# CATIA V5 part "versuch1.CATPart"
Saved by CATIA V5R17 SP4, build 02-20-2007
Part number: Guss-Konstruktion SP
Bounding box of the stored display mesh (mm): x 0 to 266.803, y -87 to 87, z -230 to 255
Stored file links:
  D:\Dokumente und Einstellungen\Alexander\Eigene Dateien\versuch1.CATPart
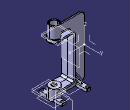
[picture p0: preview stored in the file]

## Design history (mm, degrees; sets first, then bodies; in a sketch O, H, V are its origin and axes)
AxisSystem1: origin (0, 0, 0), X (1, 0, 0), Y (0, 1, 0), Z (0, 0, 1)
Sketch1 on Plane2, origin (0, 0, 170), H (1, 0, 0), V (0, 1, 0)
  line L1 (125, 45) -> (267, 45)
  line L2 (267, 45) -> (267, -45)
  line L3 (267, -45) -> (125, -45)
  line L4 (125, -45) -> (125, 45)
  reference projected line E1 (110, -45) -> (125, -45) from edge [face of Pad2 from Sketch2.L4 | face of Pad2 from Sketch2.L1]
  reference projected line E2 (110, 45) -> (125, 45) from edge [face of Pad2 from Sketch2.L1 | face of Pad2 from Sketch2.L2]
  reference projected line E3 (125, 60) -> (125, -60) from edge [face of Pad2 from Sketch2.L1 | end face of Pad2]
  length L3 = 142
  horizontal: L1 H, L3 H
  vertical: L2 V, L4 V
  coincidence: L3 E1, L1 E2, L4 E3
Pad1: profile Sketch1, direction (0, 0, -1), length 15
Sketch2 on face of Pad3 from Sketch3.L14, origin (110, 0, 0), H (0, 1, 0), V (0, 0, 1)
  line L1 (-45, 170) -> (45, 170)
  line L2 (45, 170) -> (45, -170)
  line L3 (45, -170) -> (-45, -170)
  line L4 (-45, -170) -> (-45, 170)
  reference intersected line E1 through (0, 170) direction (-1, 0) from Plane2
  length L3 = 90
  horizontal: L1 H, L3 H
  vertical: L2 V, L4 V
  symmetry: L3 L1 H, L2 L4 V
  coincidence: L1 E1
Pad2: profile Sketch2, direction (1, 0, 0), length 15
Set1
  Plane1: type Offset, RefPlane face of Pad3 from Sketch3.L13, Offset 0
  Plane2: type Offset, RefPlane face of Pad3 from Sketch3.L15, Offset 0, reversed
  Plane3: type Offset, RefPlane face of Pad3 from Sketch3.L14, Offset 0
  Plane4: type Offset, RefPlane Plane2, Offset 10, reversed
  Plane5: type Offset, RefPlane Plane1, Offset 15, reversed
  Plane6: type Offset, RefPlane face of Pad3 from Sketch3.L11, Offset 0, reversed
  Plane7: type Offset, RefPlane face of Pad8 from Sketch12.L8, Offset 17.5
  Plane8: type Offset, RefPlane face of Pad8, Offset 0, reversed
Body1 (main body)
  Sketch3 on zx-plane, origin (0, 0, 0), H (-1, 0, 0), V (0, 0, 1)
    construction line L1 (-192, 230) -> (0, 230)
    point P1 (0, 230)
    construction line L2 (0, 230) -> (0, -230)
    construction line L3 (0, -230) -> (-265, -230)
    construction line L4 (-265, -230) -> (-265, -170)
    construction line L5 (-265, -170) -> (-110, -170)
    construction line L6 (-110, -170) -> (-110, 170)
    construction line L7 (-110, 170) -> (-192, 170)
    construction line L8 (-192, 170) -> (-192, 230)
    line L9 (-192, 230) -> (0, 230)
    line L10 (0, 230) -> (0, -230)
    line L11 (0, -230) -> (-265, -230)
    line L12 (-265, -230) -> (-265, -170)
    line L13 (-265, -170) -> (-110, -170)
    line L14 (-110, -170) -> (-110, 170)
    line L15 (-110, 170) -> (-192, 170)
    line L16 (-192, 170) -> (-192, 230)
    reference projected line E1 through (0, 0) direction (-1, 0) from edge [XY plane of AxisSystem1 | ZX plane of AxisSystem1]
    reference intersected line E2 through (0, 0) direction (-1, 0) from XY plane of AxisSystem1
    distance L14 L10 = 110
    distance L13 L11 = 60
    distance L16 L10 = 192
    length L10 = 460
    length L11 = 265
    coincidence: P1 V
    horizontal: L1 H, L3 H, L5 H, L7 H, L9 H, L11 H, L13 H, L15 H
    vertical: L2 V, L4 V, L6 V, L8 V, L10 V, L12 V, L14 V, L16 V
    symmetry: L15 L13 E1, L9 L11 E2
  Pad3: profile Sketch3, direction (0, 1, 0), length 6, mirrored extent
  Fillet1: radius 40, on edge [face of Pad3 from Sketch3.L10 | face of Pad3 from Sketch3.L11]
  Fillet2: radius 40, on edge [face of Pad3 from Sketch3.L9 | face of Pad3 from Sketch3.L10]
  Fillet3: radius 12, on edge [end face of Pad1 | end face of Pad2]
  Fillet4: radius 27, on edge [start face of Pad2 | face of Pad1] (x2)
  Sketch4 on Plane4, origin (0, 0, 160), H (1, 0, 0), V (0, 1, 0)
    circle A1 centre (224.8029, 0) radius 42
    point P1 (224.8029, 0)
    point P2 (182.8029, 0)
    circle A2 centre (224.8029, 0) radius 26
    radius A1 = 42
    radius A2 = 26
    coincidence: P1 H, A1 P2, P2 H
  Pad4: profile Sketch4, direction (0, 0, -1), length 15
  Sketch5 on Plane4, origin (0, 0, 160), H (1, 0, 0), V (0, 1, 0)
    line L1 (217.723, 45) -> (234.8496, 40.7807)
    point P1 (217.723, 45)
    point P2 (234.8496, 40.7807)
    reference projected line E1 (267, 45) -> (125, 45) from edge [end face of Pad1 | face of Pad1]
    reference projected circle E2 centre (224.8029, 0) radius 42 from edge [face of Pad4 from Sketch4.A1 | end face of Pad1]
    reference projected circle E3 centre (224.8029, 0) radius 42 from edge [face of Pad4 from Sketch4.A1 | end face of Pad1]
    line L2 (217.723, -45) -> (234.8496, -40.7807)
    point P3 (217.723, -45)
    point P4 (234.8496, -40.7807)
    reference projected line E4 (125, -45) -> (267, -45) from edge [end face of Pad1 | face of Pad1]
    reference projected circle E5 centre (224.8029, 0) radius 42 from edge [face of Pad4 from Sketch4.A1 | end face of Pad1]
    reference projected circle E6 centre (224.8029, 0) radius 42 from edge [face of Pad4 from Sketch4.A1 | end face of Pad1]
    arc A1 centre (224.8029, 0) radius 42 from (234.8496, -40.7807) to (234.8496, 40.7807) ccw
    point P5 (224.8029, 0)
    reference projected circle E7 centre (224.8029, 0) radius 26 from edge [end face of Pad1 | face of Pad4 from Sketch4.A2]
    line L3 (217.723, -45) -> (267.8976, -45)
    line L4 (267.8976, -45) -> (267.8976, 45)
    line L5 (267.8976, 45) -> (217.723, 45)
    coincidence: P1 E1, P2 E2, P3 E4, P4 E5, P5 H
    tangency: L1 E3, L2 E6
    concentricity: A1 E7
    horizontal: L3 H, L5 H
    vertical: L4 V
  Pocket1: profile Sketch5, direction (0, 0, 1), length 10, mirrored extent
  Sketch6 on end face of Pad1, origin (217.5608, 1.8006, 155), H (1, 0, 0), V (0, -1, 0)
    point P1 (7.2421, 1.8006)
    reference projected circle E1 centre (7.2421, 1.8006) radius 26 from edge [end face of Pad1 | face of Pad4 from Sketch4.A2]
    concentricity: P1 E1
  Hole1: placed by Sketch6, at (224.8029, 0, 155) direction (0, 0, 1), diameter 52, through (limit type 6)
  Sketch7 on Plane2, origin (0, 0, 170), H (1, 0, 0), V (0, 1, 0)
    circle A1 centre (224.8029, 0) radius 36
    point P1 (224.8029, 0)
    reference projected circle E1 centre (224.8029, 0) radius 26 from edge [face of Pad1 | face of Hole1]
    circle A2 centre (224.8029, 0) radius 26
    radius A1 = 36
    radius A2 = 26
    coincidence: P1 H
    concentricity: A1 E1
  Pad5: profile Sketch7, direction (0, 0, 1), length 85
  Sketch8 on Plane1, origin (0, 0, -170), H (1, 0, 0), V (0, -1, 0)
    line L1 (265, 45) -> (125, 45)
    line L2 (125, 45) -> (125, -45)
    line L3 (125, -45) -> (265, -45)
    line L4 (265, -45) -> (265, 45)
    reference intersected line E1 through (0, 0) direction (1, 0) from ZX plane of AxisSystem1
    reference projected line E2 (125, 60) -> (125, -60) from edge [face of Pad2 from Sketch2.L3 | end face of Pad2]
    reference projected line E3 (265, 12) -> (265, -12) from edge [face of Pad3 from Sketch3.L12 | face of Pad3 from Sketch3.L13]
    length L4 = 90
    horizontal: L1 H, L3 H
    vertical: L2 V, L4 V
    symmetry: L1 L3 E1
    coincidence: L2 E2, L4 E3
  Pad6: profile Sketch8, direction (0, 0, 1), length 15
  Sketch9 on Plane1, origin (0, 0, -170), H (1, 0, 0), V (0, -1, 0)
    circle A1 centre (224.8029, 0) radius 40
    point P1 (224.8029, 0)
    point P2 (184.8029, 0)
    circle A2 centre (224.8029, 0) radius 15
    point P3 (209.8029, 0)
    reference projected circle E1 centre (224.8029, 0) radius 26 from edge [end face of Pad5 | face of Pad5 from Sketch7.A2]
    radius A1 = 40
    radius A2 = 15
    coincidence: P1 H, A1 P2, P2 H, A2 P3, P3 H
    concentricity: A1 E1
  Pad7: profile Sketch9, direction (0, 0, 1), length 25
  Sketch10 on Plane5, origin (0, 0, -155), H (1, 0, 0), V (0, -1, 0)
    line L1 (210.4501, -45) -> (234.7765, -38.7366)
    point P1 (210.4501, -45)
    point P2 (234.7765, -38.7366)
    reference projected line E1 (125, -45) -> (265, -45) from edge [end face of Pad6 | face of Pad6]
    reference projected circle E2 centre (224.8029, 0) radius 40 from edge [face of Pad7 from Sketch9.A1 | end face of Pad6]
    reference projected circle E3 centre (224.8029, 0) radius 40 from edge [face of Pad7 from Sketch9.A1 | end face of Pad6]
    line L2 (208.5936, 45) -> (234.1002, 38.9045)
    point P3 (208.5936, 45)
    point P4 (234.1002, 38.9045)
    reference projected line E4 (265, 45) -> (125, 45) from edge [end face of Pad6 | face of Pad6]
    reference projected circle E5 centre (224.8029, 0) radius 40 from edge [face of Pad7 from Sketch9.A1 | end face of Pad6]
    reference projected circle E6 centre (224.8029, 0) radius 40 from edge [face of Pad7 from Sketch9.A1 | end face of Pad6]
    arc A1 centre (224.8029, 0) radius 40 from (234.7765, -38.7366) to (234.1002, 38.9045) ccw
    point P5 (224.8029, 0)
    point P6 (234.7765, -38.7366)
    reference projected circle E7 centre (224.8029, 0) radius 15 from edge [end face of Pad6 | face of Pad7 from Sketch9.A2]
    line L3 (210.4501, -45) -> (266.7285, -45)
    line L4 (266.7285, -45) -> (266.7285, 45)
    line L5 (266.7285, 45) -> (208.5936, 45)
    coincidence: P1 E1, P2 E2, P3 E4, P4 E5, P5 H, P6 L1, P2 P6
    tangency: L1 E3, L2 E6
    concentricity: A1 E7
    horizontal: L3 H, L5 H
    vertical: L4 V
  Pocket2: profile Sketch10, direction (0, 0, -1), through (limit type 6)
  Fillet5: radius 12, on edge [end face of Pad6 | end face of Pad2]
  Fillet6: radius 27, on edge [start face of Pad2 | face of Pad7] (x2)
  Sketch11 on end face of Pad6, origin (218.285, 2.7316, -155), H (1, 0, 0), V (0, 1, 0)
    point P1 (6.5179, -2.7316)
    reference projected circle E1 centre (6.5179, -2.7316) radius 15 from edge [end face of Pad6 | face of Pad7 from Sketch9.A2]
    concentricity: P1 E1
  Hole2: placed by Sketch11, at (224.8029, 0, -155) direction (0, 0, -1), diameter 30, depth 20
  Draft1: PullDir ZX plane of AxisSystem1, Parting ZX plane of AxisSystem1, Angle 2, SupportToDraft start face of Pad2, Neutral ZX plane of AxisSystem1
  Draft2: PullDir ZX plane of AxisSystem1, Parting ZX plane of AxisSystem1, Angle 2, SupportToDraft start face of Pad2, Neutral ZX plane of AxisSystem1
  Draft3: PullDir ZX plane of AxisSystem1, Parting ZX plane of AxisSystem1, Angle 2, SupportToDraft end face of Pad2, Neutral ZX plane of AxisSystem1
  Draft4: PullDir ZX plane of AxisSystem1, Parting ZX plane of AxisSystem1, Angle 2, SupportToDraft end face of Pad2, Neutral ZX plane of AxisSystem1
  Sketch12 on Plane6, origin (0, 0, -230), H (1, 0, 0), V (0, 1, 0)
    line L1 (70, 87) -> (35, 87)
    line L2 (35, 87) -> (35, -87)
    line L3 (35, -87) -> (70, -87)
    line L4 (70, -87) -> (70, 87)
    reference intersected line E1 through (0, 0) direction (-1, 0) from ZX plane of AxisSystem1
    reference intersected line E2 through (110, 0) direction (0, -1) from Plane3
    point P5 (254.8029, 87)
    line L5 (254.8029, 87) -> (219.8029, 87)
    line L6 (219.8029, 87) -> (219.8029, -87)
    line L7 (219.8029, -87) -> (254.8029, -87)
    line L8 (254.8029, -87) -> (254.8029, 87)
    point P7 (219.8029, -87)
    reference projected arc E3 centre (224.8029, 0) radius 40 from (262.9605, -12) to (262.9605, 12) ccw from edge [face of Pad3 from Sketch3.L11 | face of Pocket2 from Sketch10.A1]
    distance L4 E2 = 40
    length L2 = 174
    length L3 = 35
    length L7 = 35
    distance L8 E3 = 10
    horizontal: L1 H, L3 H, L5 H, L7 H
    vertical: L2 V, L4 V, L6 V, L8 V
    symmetry: L3 L1 E1
    coincidence: P5 L1, P7 L3
  Pad8: profile Sketch12, direction (0, 0, 1), length 20
  Sketch13 on ZX plane of AxisSystem1, origin (0, 0, 0), H (0, 0, 1), V (1, 0, 0)
    line L1 (-210, 46.5) -> (-185.6547, 46.5)
    line L2 (-185.6547, 46.5) -> (-122.8649, 85.2538)
    line L3 (-122.8649, 85.2538) -> (-122.8649, 111.5714)
    line L4 (-122.8649, 111.5714) -> (-134.8649, 111.5714)
    line L5 (-134.8649, 111.5714) -> (-134.8649, 91.949)
    line L6 (-134.8649, 91.949) -> (-189.0597, 58.5)
    line L7 (-189.0597, 58.5) -> (-210, 58.5)
    line L8 (-210, 58.5) -> (-210, 46.5)
    reference projected line E1 (-210, 100) -> (-210, 65) from edge [face of Pad8 from Sketch12.L1 | end face of Pad8]
    reference projected line E2 (-143, 111.5714) -> (143, 111.5714) from edge [start face of Pad2 | face of Pad6]
    reference projected line E3 (-230, 70) -> (-210, 70) from edge [face of Pad8 from Sketch12.L1 | face of Pad8 from Sketch12.L4]
    length L8 = 12
    length L4 = 12
    distance L7 E3 = 11.5
    distance L2 L6 = 12
    horizontal: L1 H, L4 H, L7 H
    vertical: L3 V, L5 V, L8 V
    coincidence: L8 E1, L4 E2
  Pad9: profile Sketch13, direction (0, 1, 0), length 35, mirrored extent
  Fillet7: radius 21, on edge [face of Pad9 from Sketch13.L3 | face of Pad9 from Sketch13.L2] (x2)
  Fillet8: radius 9, on edge [face of Pad9 from Sketch13.L6 | face of Pad9 from Sketch13.L5] (x2)
  Fillet9: radius 4, on edge [face of Pad9 from Sketch13.L2 | face of Pad9 from Sketch13.L1] (x2)
  Fillet10: radius 4, on edge [face of Pad9 from Sketch13.L7 | face of Pad9 from Sketch13.L6] (x2)
  Sketch14 on Plane5, origin (0, 0, -155), H (1, 0, 0), V (0, -1, 0)
    circle A1 centre (224.8029, 0) radius 40
    point P1 (224.8029, 0)
    reference projected circle E1 centre (224.8029, 0) radius 15 from edge [face of Hole2 | face of Pad7 from Sketch9.A2]
    circle A2 centre (224.8029, 0) radius 30
    point P2 (194.8029, 0)
    reference projected arc E2 centre (224.8029, 0) radius 40 from (234.7765, -38.7366) to (234.1002, 38.9045) ccw from edge [face of Pocket2 from Sketch10.A1 | face of Pad7 from Sketch9.A1]
    radius A2 = 30
    coincidence: P1 H, A2 P2, P2 H, A1 E2
    concentricity: A1 E1
  Pad10: profile Sketch14, direction (0, 0, -1), up to Plane8
  Sketch15 on face of Pad8, origin (225.1676, -0.6929, -230), H (1, 0, 0), V (0, -1, 0)
    point P1 (-0.3647, -0.6929)
    reference projected circle E1 centre (-0.3647, -0.6929) radius 30 from edge [face of Pad10 from Sketch14.A2 | face of Pad8]
    concentricity: P1 E1
  Hole3: placed by Sketch15, at (224.8029, 0, -230) direction (0, 0, 1), diameter 60, depth 65
  Sketch16 on end face of Pad4, origin (259.6675, -5.0987, 145), H (1, 0, 0), V (0, -1, 0)
    point P1 (-1.8646, -5.0987)
    reference projected line E1 through (0, -5.0987) direction (1, 0) from edge [XY plane of AxisSystem1 | ZX plane of AxisSystem1]
    reference projected circle E2 centre (-34.8646, -5.0987) radius 42 from edge [end face of Pad4 | face of Pad4 from Sketch4.A1]
    distance E2 P1 = 9
    coincidence: P1 E1
  Hole4: placed by Sketch16, at (257.8029, 0, 145) direction (0, 0, 1), diameter 6.647, depth 15, V-bottom angle 120, threaded "M8", thread diameter 8, thread depth 8, pitch 1.25
  CircPattern1: of Hole4, instances 4, angular step 90, axis from end face of Pad4
  Fillet11: radius 4, on edge [face of Pad6 | face of Pocket1 from Sketch5.L1]; edge [face of Pocket1 from Sketch5.L2 | face of Pad6]; edge [face of Pad6 | face of Pocket2 from Sketch10.L2]; edge [face of Pocket2 from Sketch10.L1 | face of Pad6]
  Draft5: PullDir ZX plane of AxisSystem1, Parting ZX plane of AxisSystem1, Angle 2, SupportToDraft face of Pad9 from Sketch13.L6, Neutral ZX plane of AxisSystem1
  Draft6: PullDir ZX plane of AxisSystem1, Parting ZX plane of AxisSystem1, Angle 2, SupportToDraft face of Pad9 from Sketch13.L2, Neutral ZX plane of AxisSystem1
  Draft7: PullDir ZX plane of AxisSystem1, Parting ZX plane of AxisSystem1, Angle 2, SupportToDraft (face of Pad9 from Sketch13.L6; face of Pad9 from Sketch13.L2), Neutral ZX plane of AxisSystem1
  Sketch17 on end face of Pad8, origin (236.3277, -67.2732, -210), H (1, 0, 0), V (0, 1, 0)
    point P1 (0.9752, -7.7268)
    reference projected line E1 (18.4752, -17.7268) -> (18.4752, 152.2732) from edge [face of Pad8 from Sketch12.L8 | end face of Pad8]
    reference projected line E2 (-16.5248, -19.7268) -> (18.4752, -19.7268) from edge [face of Pad8 from Sketch12.L7 | end face of Pad8]
    distance P1 E1 = 17.5
    distance P1 E2 = 12
  Hole5: placed by Sketch17, at (237.3029, -75, -210) direction (0, 0, -1), diameter 17, through (limit type 6)
  RectPattern1: of Hole5, direction 1 instances 2, spacing 185, along end face of Pad8 reversed, direction 2 instances 2, spacing 146, along end face of Pad8
  Fillet12: radius 5, on edge [start face of Pad3 | face of Pad3 from Sketch3.L10]; edge [face of Pad3 from Sketch3.L10 | end face of Pad3]
  Fillet13: radius 5, on edge [start face of Pad2 | end face of Pad3]; edge [face of Fillet7 | end face of Pad3]; edge [face of Pad9 from Sketch13.L3 | end face of Pad3]; edge [face of Pad9 from Sketch13.L3 | start face of Pad2] (x2); edge [start face of Pad2 | start face of Pad3]; edge [face of Fillet7 | start face of Pad3]; edge [face of Pad9 from Sketch13.L3 | start face of Pad3], deactivated
  Fillet14: radius 5, on edge [face of Pad9 from Sketch13.L6 | start face of Pad3]; edge [face of Pad9 from Sketch13.L6 | end face of Pad3]; edge [face of Pad7 | end face of Pad3]; edge [face of Pad7 | start face of Pad3]
  Fillet15: radius 5, on edge [face of Pad9 from Sketch13.L5 | start face of Pad2] (x2); edge [face of Fillet14 | face of Fillet14] (x2), deactivated
  Fillet16: radius 5, on edge [end face of Pad9 | start face of Pad2]; edge [start face of Pad9 | start face of Pad2], deactivated
  Fillet17: radius 5, on edge [face of Pad10 | end face of Pad3]; edge [start face of Pad3 | face of Pad10]
  Draft8: PullDir ZX plane of AxisSystem1, Parting ZX plane of AxisSystem1, Angle 2, SupportToDraft (face of Pad8 from Sketch12.L2; face of Pad8 from Sketch12.L6; face of Pad8 from Sketch12.L4; face of Pad8 from Sketch12.L8), Neutral ZX plane of AxisSystem1
  Draft9: PullDir ZX plane of AxisSystem1, Parting ZX plane of AxisSystem1, Angle 2, SupportToDraft (face of Pad8 from Sketch12.L8; face of Pad8 from Sketch12.L4; face of Pad8 from Sketch12.L2; face of Pad8 from Sketch12.L6), Neutral ZX plane of AxisSystem1
  Fillet18: radius 5, on edge [face of Pad8 | end face of Pad3]
  Fillet19: radius 5, on edge [face of Pad8 | face of Pad10]
  Fillet20: radius 3, on edge [face of Pad10 from Sketch14.A2 | face of Pad8]; edge [face of Hole3 | face of Pad8]
  Fillet21: radius 3, on edge [face of Pad7 from Sketch9.A2 | end face of Pad7]; edge [end face of Pad7 | face of Pad10]
  Fillet22: radius 3, on edge [end face of Pad5 | face of Pad5 from Sketch7.A2]; edge [face of Pad5 from Sketch7.A1 | end face of Pad5]
  Fillet23: radius 2, on edge [end face of Pad4 | face of Pad4 from Sketch4.A1]; edge [face of Pad4 from Sketch4.A2 | end face of Pad4]
  Fillet24: radius 2, on edge [start face of Pad3 | face of Pad5 from Sketch7.A1], deactivated
  Fillet25: radius 3, on edge [face of Hole2 | face of Hole3]
  Fillet26: radius 5, on edge [face of Hole3 | face of Hole3]
  Fillet27: radius 3, on face of Pad8 from Sketch12.L1; face of Pad8 from Sketch12.L5; face of Pad8 from Sketch12.L7; face of Pad8 from Sketch12.L3
  Fillet28: radius 5, on edge [face of Pad9 from Sketch13.L2 | start face of Pad3]
  Fillet29: radius 5, on edge [face of Pad9 from Sketch13.L2 | end face of Pad3]; edge [start face of Pad2 | end face of Pad3]; edge [face of Pad9 from Sketch13.L3 | start face of Pad2] (x2); edge [start face of Pad2 | start face of Pad3]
